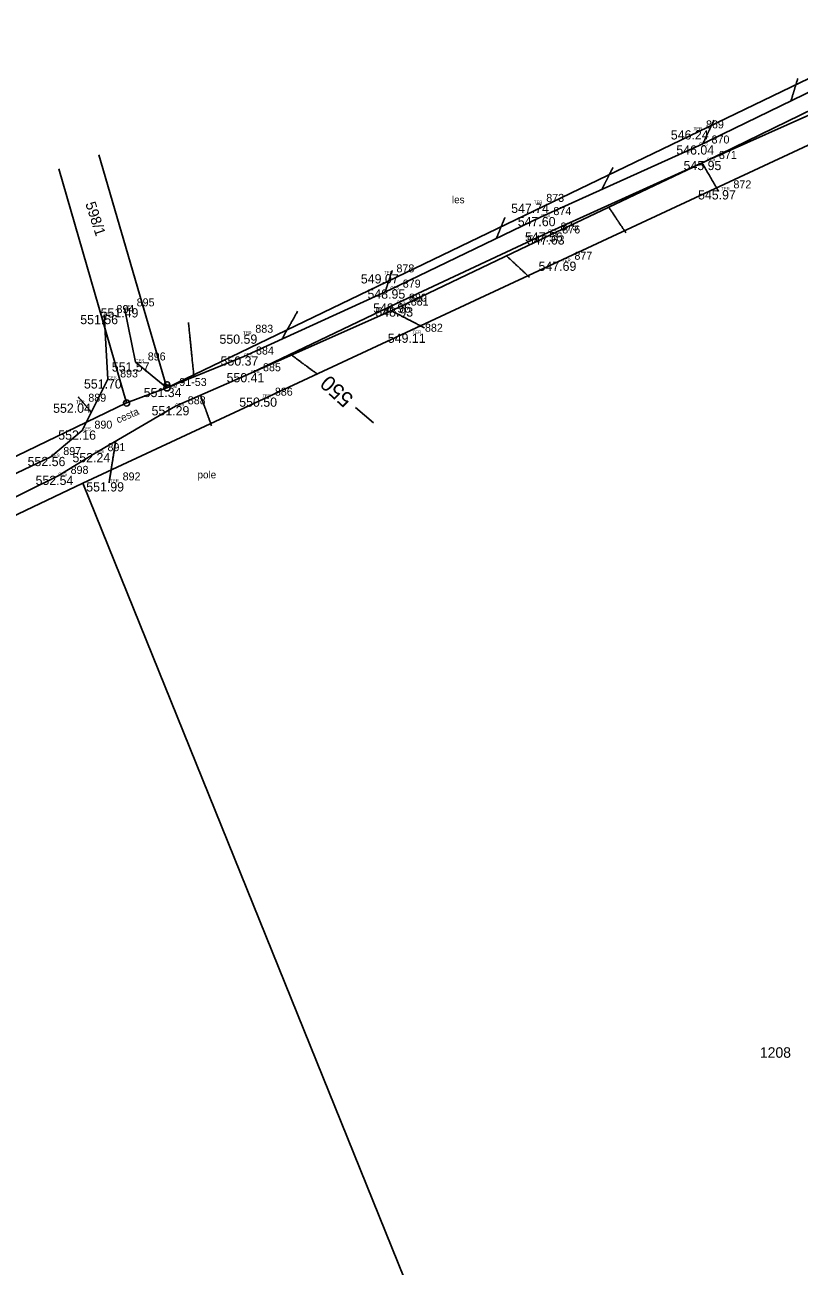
# Model space of a CAD drawing. Extents: x -604848 to -603227, y -1111879 to -1109838.
# Drawn here: x -604694.2 to -604568.4, y -1111354 to -1111152.4 of the extents above; entities that cross this region are included whole.
import ezdxf

# ---------------------------------------------------------------- set-up
doc = ezdxf.new("R2010")
doc.units = 0
for name, color, linetype in [('1', 7, 'Continuous'), ('10', 7, 'Continuous'), ('14', 7, 'Continuous'), ('18', 7, 'Continuous'), ('19', 7, 'Continuous'), ('20', 7, 'Continuous'), ('28', 7, 'Continuous'), ('4', 7, 'Continuous'), ('7', 7, 'Continuous'), ('9', 7, 'Continuous'), ('Default', 7, 'Continuous')]:
    doc.layers.add(name, color=color, linetype=linetype)

# ---------------------------------------------------------------- blocks, each defined once
blk = doc.blocks.new('Z105')
at = {"layer": '28'}
for radius in [0.5, 0.01]:
    blk.add_circle((0, 0), radius, dxfattribs=at)
blk = doc.blocks.new('POINT_DISPLAY')
at = {"layer": 'Default'}
blk.add_line((0, 0), (0, 0), dxfattribs=at)
blk = doc.blocks.new('Z4')
at = {"layer": '4'}
for p, q in [((-0.4, 0.7), (-0.3, 0.9)), ((-0.4, 0.3), (-0.4, 0.7)), ((-0.3, 0.9), (-0.1, 1)), ((-0.1, 1), (0.1, 1)), ((0.1, 1), (0.3, 0.9)), ((0.3, 0.9), (0.4, 0.7)), ((0.4, 0.7), (0.4, 0.3))]:
    blk.add_line(p, q, dxfattribs=at)

msp = doc.modelspace()

# ---------------------------------------------------------------- linework, layer by layer
at = {"layer": '1'}
for p, q in [((-604548.87, -1111152.42), (-604671.12, -1111211.37)), ((-604684.78, -1111226.85), (-604556.81, -1111167.23)), ((-604671.12, -1111211.37), (-604682.16, -1111173.53)), ((-604677.69, -1111213.82), (-604688.66, -1111175.81)), ((-604671.12, -1111211.37), (-604677.69, -1111213.82)), ((-604677.69, -1111213.82), (-604726.13, -1111237.1)), ((-604741.99, -1111253.97), (-604684.78, -1111226.85)), ((-604684.78, -1111226.85), (-604617.61, -1111392.95))]:
    msp.add_line(p, q, dxfattribs=at)
at = {"layer": '10'}
for p, q in [((-604558.89, -1111163.5), (-604583.48, -1111174.51)), ((-604583.48, -1111174.51), (-604608.92, -1111186.6)), ((-604608.92, -1111186.6), (-604633.53, -1111198.3)), ((-604633.53, -1111198.3), (-604657.52, -1111208.97))]:
    msp.add_line(p, q, dxfattribs=at)
at = {"layer": '4'}
for p, q in [((-604584.67, -1111171.99), (-604560.36, -1111160.19)), ((-604559.22, -1111162.63), (-604583.48, -1111174.51)), ((-604610.36, -1111183.62), (-604584.67, -1111171.99)), ((-604583.48, -1111174.51), (-604609.2, -1111186.13)), ((-604634.82, -1111195.39), (-604610.36, -1111183.62)), ((-604609.2, -1111186.13), (-604633.82, -1111197.67)), ((-604658.66, -1111206.26), (-604634.82, -1111195.39)), ((-604681.32, -1111199.53), (-604680.73, -1111209.98)), ((-604676.24, -1111207.22), (-604678.04, -1111198.44)), ((-604633.82, -1111197.67), (-604657.52, -1111208.97)), ((-604671.12, -1111211.37), (-604676.24, -1111207.22)), ((-604658.66, -1111206.26), (-604671.12, -1111211.37)), ((-604657.52, -1111208.97), (-604669.74, -1111214.34)), ((-604680.73, -1111209.98), (-604684.9, -1111218.29)), ((-604669.74, -1111214.34), (-604682.78, -1111221.95)), ((-604684.9, -1111218.29), (-604689.96, -1111222.58)), ((-604707.4, -1111230.84), (-604689.96, -1111222.58)), ((-604682.78, -1111221.95), (-604688.77, -1111225.64)), ((-604688.77, -1111225.64), (-604706.04, -1111234.13))]:
    msp.add_line(p, q, dxfattribs=at)
at = {"layer": '7'}
msp.add_line((-604637.56, -1111217.03), (-604640.52, -1111214.57), dxfattribs=at)
for points in [[(-604569.78, -1111164.76), (-604569.41, -1111163.56), (-604569.05, -1111162.35), (-604568.68, -1111161.14)], [(-604584.07, -1111171.7), (-604583.47, -1111170.43), (-604582.88, -1111169.17), (-604582.29, -1111167.9)], [(-604584.2, -1111174.84), (-604583.31, -1111176.38), (-604582.42, -1111177.93), (-604581.53, -1111179.47)], [(-604598.68, -1111175.57), (-604599.29, -1111176.76), (-604599.89, -1111177.96), (-604600.49, -1111179.15)], [(-604599.35, -1111182.06), (-604598.43, -1111183.44), (-604597.5, -1111184.83), (-604596.58, -1111186.22)], [(-604616.23, -1111183.69), (-604616.7, -1111184.83), (-604617.16, -1111185.97), (-604617.62, -1111187.11)], [(-604615.96, -1111189.95), (-604614.72, -1111191.11), (-604613.48, -1111192.26), (-604612.25, -1111193.42)], [(-604635.69, -1111195.79), (-604635.31, -1111194.62), (-604634.92, -1111193.46), (-604634.53, -1111192.3)], [(-604652.41, -1111203.41), (-604651.58, -1111201.92), (-604650.74, -1111200.42), (-604649.91, -1111198.93)], [(-604634.72, -1111198.83), (-604632.91, -1111199.76), (-604631.11, -1111200.7), (-604629.3, -1111201.63)], [(-604666.74, -1111209.57), (-604667.04, -1111206.63), (-604667.33, -1111203.69), (-604667.63, -1111200.75)], [(-604650.92, -1111206.03), (-604649.52, -1111207.06), (-604648.13, -1111208.09), (-604646.73, -1111209.12)], [(-604683.4, -1111215.31), (-604684.12, -1111214.48), (-604684.83, -1111213.66), (-604685.55, -1111212.83)], [(-604665.69, -1111212.56), (-604665.08, -1111214.22), (-604664.48, -1111215.88), (-604663.87, -1111217.54)], [(-604679.45, -1111220.01), (-604679.81, -1111222.27), (-604680.16, -1111224.54), (-604680.52, -1111226.8)]]:
    msp.add_open_spline(points, degree=2, dxfattribs=at)

# ---------------------------------------------------------------- block references
at = {"layer": '18'}
for p in [(-604585.58, -1111169.54), (-604584.67, -1111171.99), (-604583.48, -1111174.51), (-604581.12, -1111179.28), (-604611.52, -1111181.47), (-604610.36, -1111183.62), (-604609.2, -1111186.13), (-604608.92, -1111186.6), (-604606.95, -1111190.87), (-604635.85, -1111192.92), (-604634.82, -1111195.39), (-604681.32, -1111199.53), (-604678.04, -1111198.44), (-604633.82, -1111197.67), (-604633.53, -1111198.3), (-604658.77, -1111202.71), (-604631.22, -1111202.56), (-604676.24, -1111207.22), (-604658.66, -1111206.26), (-604657.52, -1111208.97), (-604680.73, -1111209.98), (-604671.12, -1111211.37), (-604655.6, -1111212.94), (-604685.89, -1111213.92), (-604669.74, -1111214.34), (-604684.9, -1111218.29), (-604689.96, -1111222.58), (-604682.78, -1111221.95), (-604688.77, -1111225.64), (-604680.32, -1111226.7)]:
    msp.add_blockref('POINT_DISPLAY', p, dxfattribs=at)
at = {"layer": '28'}
for p in [(-604671.12, -1111211.37), (-604677.69, -1111213.82)]:
    msp.add_blockref('Z105', p, dxfattribs=at)
at = {"layer": '4'}
msp.add_blockref('Z4', (-604671.12, -1111211.37), dxfattribs=at)

# ---------------------------------------------------------------- texts
at = {"layer": '14'}
msp.add_text('598/1', height=1.7, rotation=288, dxfattribs=at).set_placement((-604684.4, -1111181.46))
msp.add_text('1208', height=1.7, dxfattribs=at).set_placement((-604574.83, -1111320.15))
at = {"layer": '18'}
for s, p in [('TER', (-604585.58, -1111169.54)), ('CES', (-604584.67, -1111171.99)), ('CES', (-604583.48, -1111174.51)), ('TER', (-604581.12, -1111179.28)), ('TER', (-604611.52, -1111181.47)), ('CES', (-604610.36, -1111183.62)), ('CES', (-604609.2, -1111186.13)), ('POL', (-604608.92, -1111186.6)), ('TER', (-604606.95, -1111190.87)), ('TER', (-604635.85, -1111192.92)), ('CES', (-604634.82, -1111195.39)), ('CES', (-604633.82, -1111197.67)), ('CES', (-604681.32, -1111199.53)), ('CES', (-604678.04, -1111198.44)), ('POL', (-604633.53, -1111198.3)), ('TER', (-604658.77, -1111202.71)), ('TER', (-604631.22, -1111202.56)), ('CES', (-604676.24, -1111207.22)), ('CES', (-604658.66, -1111206.26)), ('CES', (-604680.73, -1111209.98)), ('CES', (-604657.52, -1111208.97)), ('UMM', (-604671.12, -1111211.37)), ('TER', (-604685.89, -1111213.92)), ('TER', (-604655.6, -1111212.94)), ('CES', (-604669.74, -1111214.34)), ('CES', (-604684.9, -1111218.29)), ('CES', (-604682.78, -1111221.95)), ('CES', (-604689.96, -1111222.58)), ('CES', (-604688.77, -1111225.64)), ('TER', (-604680.32, -1111226.7))]:
    msp.add_text(s, height=0.5, dxfattribs=at).set_placement(p)
at = {"layer": '19'}
for s, p in [('869', (-604583.58, -1111169.24)), ('870', (-604582.67, -1111171.69)), ('871', (-604581.48, -1111174.21)), ('872', (-604579.12, -1111178.98)), ('873', (-604609.52, -1111181.17)), ('874', (-604608.36, -1111183.32)), ('875', (-604607.2, -1111185.83)), ('876', (-604606.92, -1111186.3)), ('877', (-604604.95, -1111190.57)), ('878', (-604633.85, -1111192.62)), ('879', (-604632.82, -1111195.09)), ('895', (-604676.04, -1111198.14)), ('880', (-604631.82, -1111197.37)), ('881', (-604631.53, -1111198)), ('894', (-604679.32, -1111199.23)), ('883', (-604656.77, -1111202.42)), ('882', (-604629.22, -1111202.26)), ('884', (-604656.66, -1111205.96)), ('896', (-604674.24, -1111206.92)), ('885', (-604655.52, -1111208.67)), ('893', (-604678.73, -1111209.68)), ('91-53', (-604669.12, -1111211.07)), ('886', (-604653.6, -1111212.64)), ('889', (-604683.89, -1111213.62)), ('888', (-604667.74, -1111214.04)), ('890', (-604682.9, -1111217.99)), ('897', (-604687.96, -1111222.28)), ('891', (-604680.78, -1111221.65)), ('898', (-604686.77, -1111225.34)), ('892', (-604678.32, -1111226.4))]:
    msp.add_text(s, height=1.3, dxfattribs=at).set_placement(p)
at = {"layer": '20'}
for s, p in [('546.24 ', (-604589.29, -1111171.04)), ('546.04 ', (-604588.4, -1111173.49)), ('545.95 ', (-604587.22, -1111176.01)), ('545.97 ', (-604584.87, -1111180.78)), ('547.74 ', (-604615.22, -1111182.97)), ('547.60 ', (-604614.15, -1111185.12)), ('547.56 ', (-604612.98, -1111187.63)), ('547.63 ', (-604612.68, -1111188.1)), ('547.69 ', (-604610.77, -1111192.37)), ('549.07 ', (-604639.63, -1111194.42)), ('548.95 ', (-604638.56, -1111196.89)), ('551.56 ', (-604685.2, -1111201.03)), ('551.49 ', (-604681.9, -1111199.94)), ('548.96 ', (-604637.63, -1111199.17)), ('548.93 ', (-604637.28, -1111199.8)), ('550.59 ', (-604662.59, -1111204.21)), ('549.11 ', (-604635.25, -1111204.06)), ('551.57 ', (-604680.08, -1111208.72)), ('550.37 ', (-604662.42, -1111207.76)), ('550.41 ', (-604661.44, -1111210.47)), ('551.70 ', (-604684.6, -1111211.48)), ('551.34 ', (-604674.9, -1111212.87)), ('550.50 ', (-604659.38, -1111214.44)), ('552.04 ', (-604689.61, -1111215.42)), ('551.29 ', (-604673.62, -1111215.84)), ('552.16 ', (-604688.78, -1111219.79)), ('552.56 ', (-604693.75, -1111224.08)), ('552.24 ', (-604686.47, -1111223.45)), ('552.54 ', (-604692.46, -1111227.14)), ('551.99 ', (-604684.23, -1111228.2))]:
    msp.add_text(s, height=1.5, dxfattribs=at).set_placement(p)
at = {"layer": '7'}
msp.add_text('550', height=2.5, rotation=137.7, dxfattribs=at).set_placement((-604640.66, -1111212.89))
at = {"layer": '9'}
for s, p in [('les', (-604624.84, -1111181.4)), ('pole', (-604666.16, -1111226.07))]:
    msp.add_text(s, height=1.2, dxfattribs=at).set_placement(p)
msp.add_text('cesta', height=1.2, rotation=23.4, dxfattribs=at).set_placement((-604679.06, -1111217.16))

doc.saveas('drawing.dxf')
